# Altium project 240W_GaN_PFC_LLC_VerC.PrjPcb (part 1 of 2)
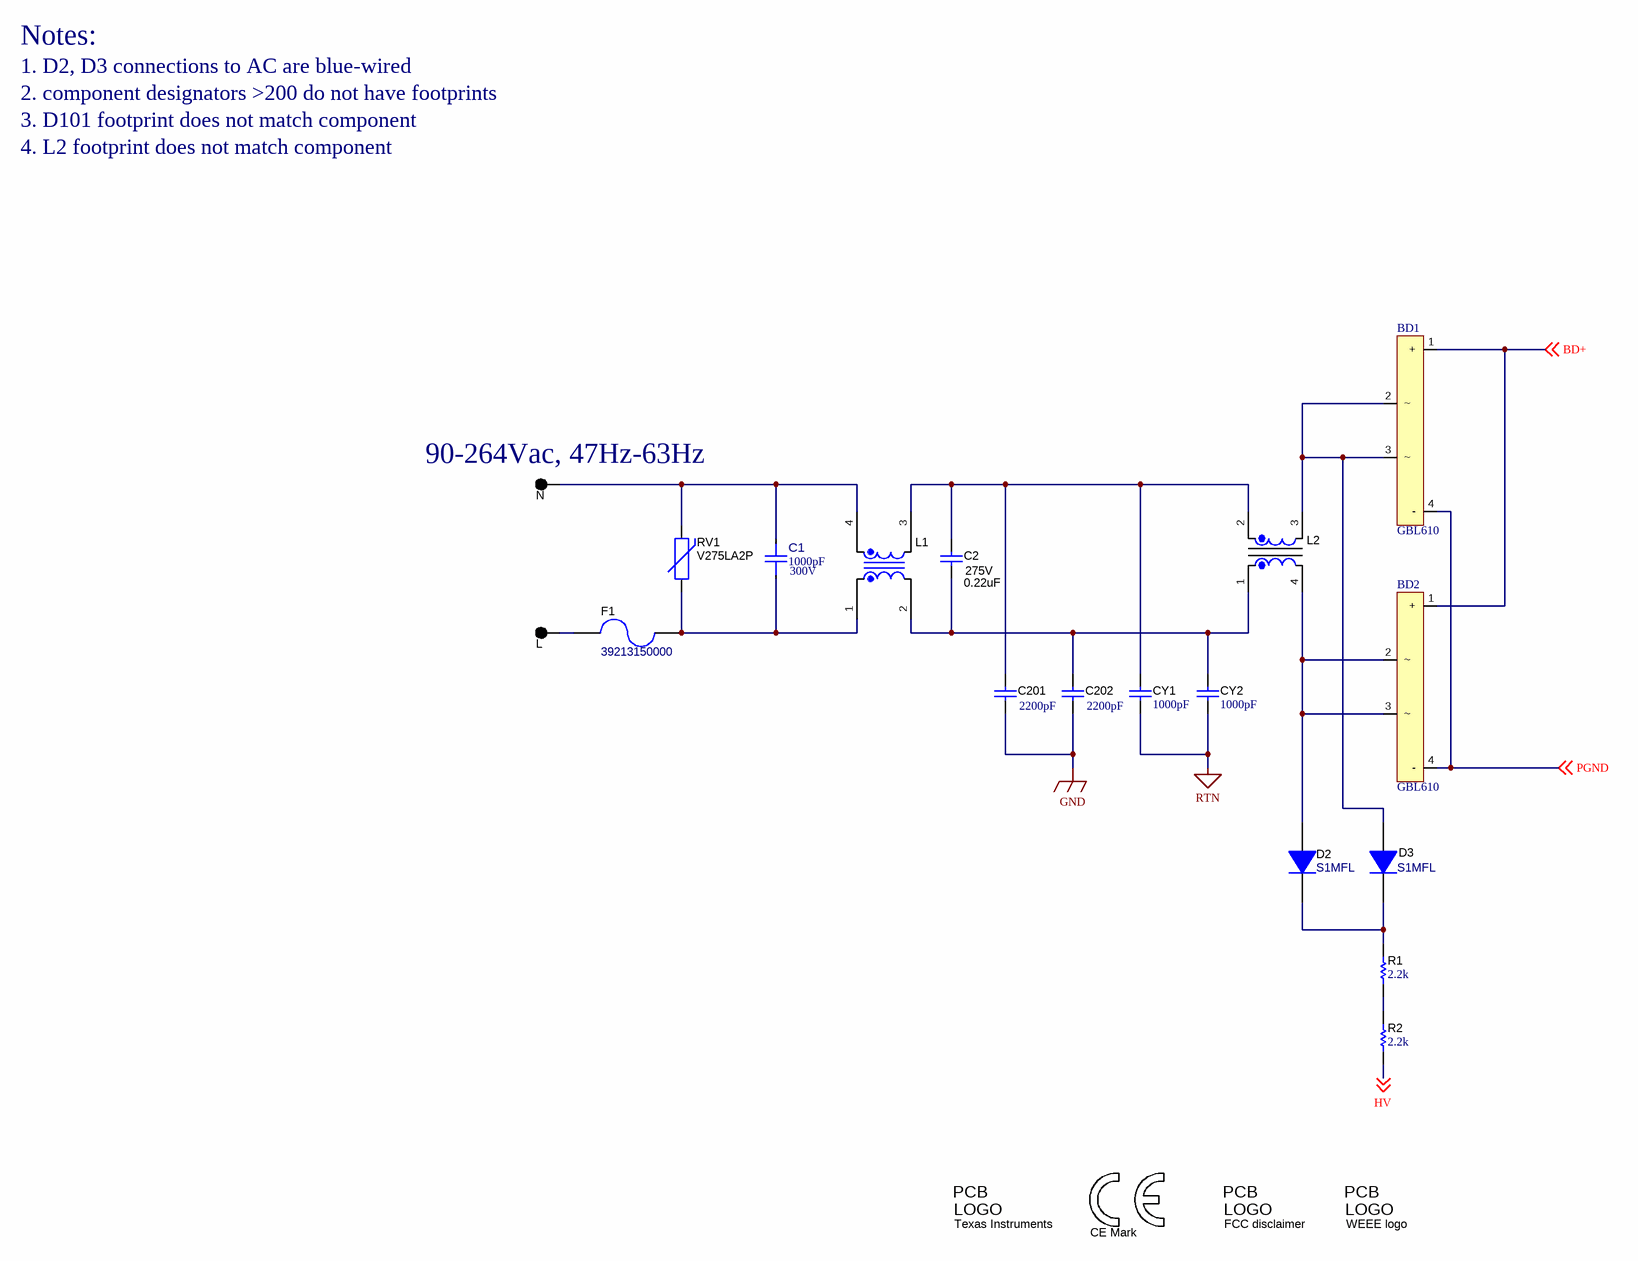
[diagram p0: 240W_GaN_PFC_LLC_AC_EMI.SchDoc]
CopyrightYear: 2024; PCB_Layout: M. Huang; PCB_Rev: C; PRJ_Engineer: M. Huang / J. Gomez; PRJ_Number: PMP23558; PRJ_Title: 240W PFC + LLC; SCH_Rev: C; TechSupport: http://www.ti.com/support; TID: N/A
3 sheets, 170 parts. Net scope: global (net labels, ports and power ports of the same name join across sheets).
Board file: 240W_GaN_PFC_LLC.PcbDoc
Sheets:
  240W_GaN_PFC_LLC_AC_EMI.SchDoc
  240W_PFC_Stage.SchDoc
  240W_LLC_Stage.SchDoc

## Sheet 240W_GaN_PFC_LLC_AC_EMI.SchDoc
size 431 x 279 mm; Date: Not shown in title block; ApprovedBy: Not shown in title block; CheckedBy: Not shown in title block; Author: Not shown in title block; CompanyName: Not shown in title block; Engineer: Not shown in title block; Organization: Not shown in title block; Address1: Not shown in title block; Address2: Not shown in title block; Address3: Not shown in title block; Address4: Not shown in title block; DocumentNumber: 1; Revision: Use project parameter SCH_Rev; SheetNumber: 1; SheetTotal: 3; PageSetup: Record=PageOptions¦CenterHorizontal=True¦CenterVertical=True¦PrintScale=1.00¦XCorrection=1.00¦YCorrection=1.00¦PrintKind=0¦BorderSize=5000000¦LeftOffset=0¦BottomOffset=0¦Orientation=2¦PaperLength=1000¦PaperWidth=1000¦Scale=100¦PaperSource=15¦PrintQuality=600¦MediaType=1¦DitherType=10¦PaperKind=Letter¦PrintScaleMode=1

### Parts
BD1  GBL610  [GBL610]
BD2  GBL610  [GBL610]
C1  ValueDisplayed: 1000pF  VAC: 300V  [FP-R413D1100JMT0K_RADIAL-MFG]  (hidden comment: R413D1100JMT0K)
C2  VDC_V: 275V  ValueDisplayed: 0.22uF  [WCAP-FTX2_1500x700x1250]  (hidden comment: 890324024002)
C201  ValueDisplayed: 2200pF  [VY2_900x500]  (hidden comment: VY2222M35Y5US63V7)
C202  ValueDisplayed: 2200pF  [VY2_900x500]  (hidden comment: VY2222M35Y5US63V7)
CY1  ValueDisplayed: 1000pF  [DK1_86]  (hidden comment: DK1E3EA102M86RAH01)
CY2  ValueDisplayed: 1000pF  [DK1_86]  (hidden comment: DK1E3EA102M86RAH01)
D2  S1MFL  [SOD-123]
D3  S1MFL  [SOD-123]
F1  39213150000  [FUSE_392]
L1  744842565  [WE-CMB_NiZn_S]  (value not drawn)
L2  (no value)  [CM_DCN181713H]
Logo1  CE Mark  [CE_Mark_5mm]  (no BOM)
Logo2  Texas Instruments  [TI_Stacked_Overlay_Small]  (no BOM)
Logo3  FCC disclaimer  [FCC_disclaimer]  (no BOM)
Logo4  WEEE logo  [WEEE_Minimum]  (no BOM)
R1  ValueDisplayed: 2.2k  [1206]  (hidden comment: CRCW12062K20JNEA)
R2  ValueDisplayed: 2.2k  [1206]  (hidden comment: CRCW12062K20JNEA)
RV1  V275LA2P  [Littelfuse_V275LA_7MM]
TP1  N  [Keystone5011]
TP2  L  [Keystone5011]

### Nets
GND: C201.2 C202.2
PGND: BD1.4(-) BD2.4(-) ; off-sheet PGND
RTN: CY1.2 CY2.2
BD+: BD1.1(+) BD2.1(+) ; off-sheet BD+
HV: R2.1 ; off-sheet HV
NetBD1_2: BD1.2 BD1.3 D3.2(A) L2.3
NetBD2_2: BD2.2 BD2.3 D2.2(A) L2.4
NetC1_1: C1.1 F1.1 L1.1 RV1.1
NetC1_2: C1.2 L1.4 RV1.2 TP1.1
NetC2_1: C2.1 C201.1 CY1.1 L1.3 L2.2
NetC2_2: C2.2 C202.1 CY2.1 L1.2 L2.1
NetD2_1: D2.1(K) D3.1(K) R1.2
NetF1_2: F1.2 TP2.1
NetR1_1: R1.1 R2.2

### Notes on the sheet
- Notes:
- 1. D2, D3 connections to AC are blue-wired
- 2. component designators >200 do not have footprints
- 3. D101 footprint does not match component
- 4. L2 footprint does not match component
- (near TP1) 90-264Vac, 47Hz-63Hz

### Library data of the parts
BD1 BD2 = BD
C1 = CMP-0047964-1: 1000 pF Film Capacitor 300V 1500V (1.5kV) Polypropylene (PP), Metallized Radial; Manufacturer: KEMET; AEC Grade: Grade 1; AEC Qualified: Yes; Cap_F: 1nF; SizeZ_mm: 9.1mm; Tolerance_%: 10%; VAC_X: X1; VAC_Y: Y2; Value: 1nF
C2 = CMP-0012312-3: CAP, Film, 0.22 uF, 275 V, +/- 10%, TH; Manufacturer: Wurth Elektronik; TaMin_C: -40°C; Polarized: N; SizeAreaWB_mm2: 153; Value1: Unknown; Value: 0.22uF; TaMax_C: 105°C; SizeZ_mm: 13; SizeX_mm: 15; SizeY_mm: 7; Cap_Case: 15x7x12.5; SizeArea_mm2: 105; Cap_F: 220nF; AEC Category: Q200
C201 C202 = CMP-0009627-2: CAP, CERM, 2200 pF, 440 V, +/- 20%, VY2, D9xT5mm; Manufacturer: Vishay-Bccomponents; TaMin_C: -40°C; Polarized: N; SizeAreaWB_mm2: 77; Value1: Unknown; U/M: EA; Value: 2200pF; TaMax_C: 125°C; SizeZ_mm: 13; SizeX_mm: 9; SizeY_mm: 5; Cap_Case: 9x5mm; Value2: 440V; SizeArea_mm2: 45; Cap_F: 2.2nF; AEC Category: Q200
CY1 CY2 = CMP-0077997-1: CAP, CERM, 1000 pF, X1 440 VAC/Y1 250 VAC, +/- 20%, E, 8x6mm; Manufacturer: MuRata; Cap_F: 1nF; VAC_X: 440; SizeAreaWB_mm2: 107.2; VAC_Y: 250; SizeArea_mm2: 68.4; AEC Qualified: N; AEC Category: Q200; Value: 1000pF; TaMax_C: 125°C; SizeZ_mm: 2.5; TaMin_C: -40°C; SizeY_mm: 6; U/M: EA; AC_Safety: X1Y1; SizeX_mm: 11.4
D2 D3 = CMP-0029032-2: Diode, GP, 1KV, 1 A, SOD-123F; Manufacturer: ON Semiconductor; Value: 1000V; Type: Switching; SizeY_mm: 1.7; Io_A: 1A; SizeAreaWB_mm2: 13.095; SizeArea_mm2: 6.545; Vf_V: 1V; TJmax_C: 150°C; SizeX_mm: 3.85; SizeZ_mm: 1.35; Green_Lifecycle: Active; Green_REACh: Passed
F1 = CMP-0003561-2: Fuse, 3.15 A, 250VAC/VDC, TH; Manufacturer: Littelfuse; Irating_A: 3.15A; VAC_V: 250V
L1 = CMP-0013095-2: Coupled inductor, 5 A, 0.013 ohm, TH; Manufacturer: Wurth Elektronik; DCR_ohm: 0.013
L2 = CM_Choke_Planar: Manufacturer: Wurth; PartNumber: 744824310
Logo1 = CMP-0074844-1: SymbolCreator: a0412235
Logo2 = CMP-0074838-1: Texas Instrument Corporate Signature; SymbolCreator: a0412235; Lib Reference: TI_Logo; Library Reference: Logo
Logo3 = CMP-0074847-1: FCC_disclaimer; Library Reference: Logo
Logo4 = CMP-0074769-1
R1 R2 = CMP-0018641-3: RES, 2.2 k, 5%, 0.25 W, AEC-Q200 Grade 0, 1206; Manufacturer: Vishay-Dale; Power_W: 250mW; TempCo: 200 ppm/C; Value_Code: 2k20; Value: 2.2k; EIA_Code: E24; SizeX_mm: 3.2; SizeY_mm: 1.6; SizeZ_mm: 1.35; Value2: 0.25W; SizeArea_mm2: 5.12; AEC Qualified: Y; VDC_V: 200V; AEC Category: Q200; AEC Grade: 0
RV1 = CMP-0001908-4: VARISTOR 450V 1.2KA DISC 7MM; Manufacturer: Littelfuse; SizeX_mm: 7; SizeArea_mm2: 39.2; SizeY_mm: 5.6; SizeAreaWB_mm2: 68.4; SizeZ_mm: 12
TP1 TP2 = CMP-0055148-1: Test Point, Multipurpose, Black, TH; Manufacturer: Keystone; CNHeader: FALSE; Green_Lifecycle: Active; Green_REACh: Passed; ContactFinish: Silver; CT: TRUE

## Sheet 240W_PFC_Stage.SchDoc
size 431 x 279 mm; Date: Not shown in title block; ApprovedBy: Not shown in title block; CheckedBy: Not shown in title block; Author: Not shown in title block; CompanyName: Not shown in title block; Engineer: Not shown in title block; Organization: Not shown in title block; Address1: Not shown in title block; Address2: Not shown in title block; Address3: Not shown in title block; Address4: Not shown in title block; DocumentNumber: 2; Revision: Use project parameter SCH_Rev; SheetNumber: 2; SheetTotal: 3; PageSetup: Record=PageOptions¦CenterHorizontal=True¦CenterVertical=True¦PrintScale=1.00¦XCorrection=1.00¦YCorrection=1.00¦PrintKind=0¦BorderSize=5000000¦LeftOffset=0¦BottomOffset=0¦Orientation=2¦PaperLength=1000¦PaperWidth=1000¦Scale=100¦PaperSource=15¦PrintQuality=600¦MediaType=1¦DitherType=10¦PaperKind=Letter¦PrintScaleMode=1
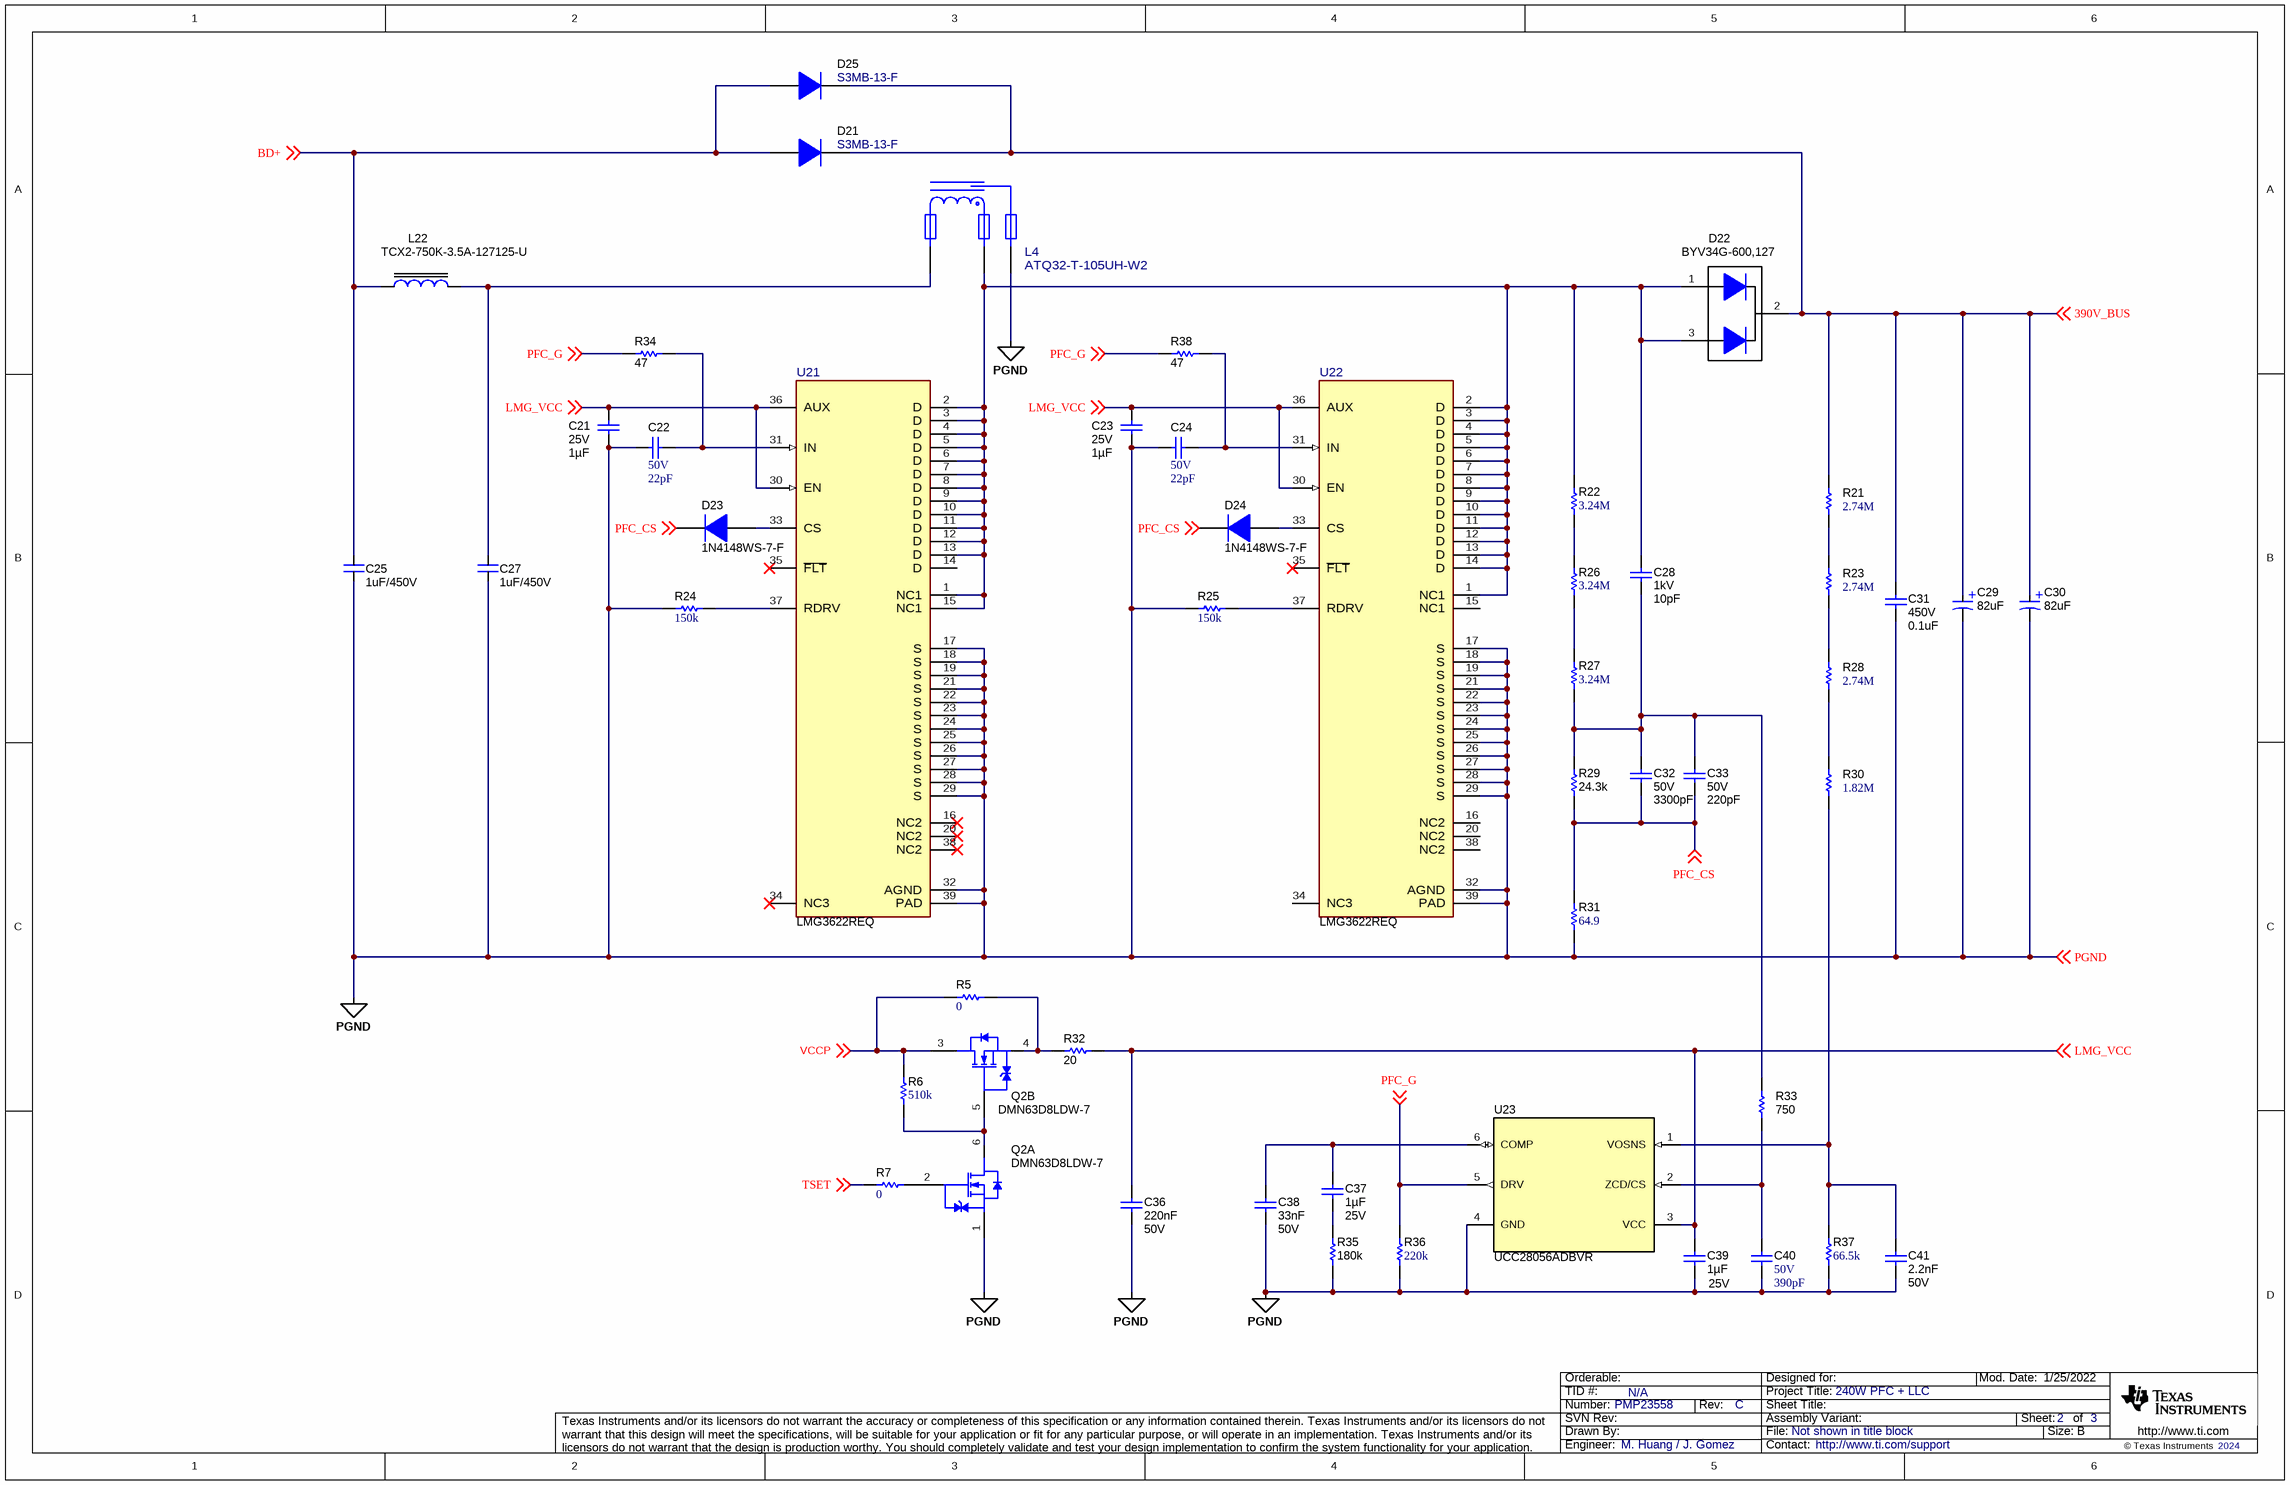
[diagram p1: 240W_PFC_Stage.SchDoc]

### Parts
C21  Cap_F: 1µF  VDC_V: 25V  [0603_HV]  (hidden comment: GRJ188R71E105KE11D)
C22  VDC_V: 50V  ValueDisplayed: 22pF  [0603_HV]  (hidden comment: CGA3E2C0G1H220J080AA)
C23  Cap_F: 1µF  VDC_V: 25V  [0603_HV]  (hidden comment: GRJ188R71E105KE11D)
C24  VDC_V: 50V  ValueDisplayed: 22pF  [0603_HV]  (hidden comment: CGA3E2C0G1H220J080AA)
C25  1uF/450V  [C_film_17.5x7]
C27  1uF/450V  [C_film_17.5x7]
C28  VDC_V: 1kV  ValueDisplayed: 10pF  [1206L]  (hidden comment: VJ1206A100JXGAT5Z)
C29  82uF  [Cap_12.5x40_H1]
C30  82uF  [Cap_12.5x40_H1]
C31  VDC_V: 450V  ValueDisplayed: 0.1uF  [1206_180]  (hidden comment: C3216X7T2W104K160AE)
C32  VDC_V: 50V  ValueDisplayed: 3300pF  [0603_HV]  (hidden comment: GRM1885C1H332JA01D)
C33  VDC_V: 50V  ValueDisplayed: 220pF  [0603_HV]  (hidden comment: GRM1885C1H221JA01D)
C36  Cap_F: 220nF  VDC_V: 50V  [0603_HV]  (hidden comment: GCM188R71H224KA64D)
C37  Cap_F: 1µF  VDC_V: 25V  [0603_HV]  (hidden comment: 06033C105KAT2A)
C38  Cap_F: 33nF  VDC_V: 50V  [0603_HV]  (hidden comment: GRM188R71H333KA61D)
C39  Cap_F: 1µF  VDC_V: 25V  [0603_HV]  (hidden comment: 06033C105KAT2A)
C40  VDC_V: 50V  ValueDisplayed: 390pF  [0603_HV]  (hidden comment: C0603C391J5GACTU)
C41  Cap_F: 2.2nF  VDC_V: 50V  [0603_HV]  (hidden comment: C0603C222K5RACTU)
D21  S3MB-13-F  [SMB]
D22  BYV34G-600,127  [TO-220AB]
D23  1N4148WS-7-F  [SOD-323]
D24  1N4148WS-7-F  [SOD-323]
D25  S3MB-13-F  [SMB]
L4  ATQ32-T-105UH-W2  [FP-202410103L250W_PTH3-MFG]
L22  TCX2-750K-3.5A-127125-U  [L_Ring_H_D=16.76mm]
Q2  DMN63D8LDW-7  [SOT-363]  (parts A,B of 2)
R5  ValueDisplayed: 0  [0603_HV]  (hidden comment: RCS06030000Z0EA)
R6  ValueDisplayed: 510k  [0603_HV]  (hidden comment: CRCW0603510KJNEA)
R7  ValueDisplayed: 0  [0603_HV]  (hidden comment: RCS06030000Z0EA)
R21  ValueDisplayed: 2.74M  [0805_HV]  (hidden comment: CRCW08052M74FKEA)
R22  ValueDisplayed: 3.24M  [0805_HV]  (hidden comment: CRCW08053M24FKEA)
R23  ValueDisplayed: 2.74M  [0805_HV]  (hidden comment: CRCW08052M74FKEA)
R24  ValueDisplayed: 150k  [0603_HV]  (hidden comment: CRCW0603150KJNEA)
R25  ValueDisplayed: 150k  [0603_HV]  (hidden comment: CRCW0603150KJNEA)
R26  ValueDisplayed: 3.24M  [0805_HV]  (hidden comment: CRCW08053M24FKEA)
R27  ValueDisplayed: 3.24M  [0805_HV]  (hidden comment: CRCW08053M24FKEA)
R28  ValueDisplayed: 2.74M  [0805_HV]  (hidden comment: CRCW08052M74FKEA)
R29  ValueDisplayed: 24.3k  [0603_HV]  (hidden comment: RC0603FR-0724K3L)
R30  ValueDisplayed: 1.82M  [0805_HV]  (hidden comment: CRCW08051M82FKEA)
R31  ValueDisplayed: 64.9  [0603]  (hidden comment: RC0603FR-0764R9L)
R32  ValueDisplayed: 20  [0603_HV]  (hidden comment: CRCW060320R0JNEA)
R33  ValueDisplayed: 750  [0603_HV]  (hidden comment: RC0603JR-07750RL)
R34  ValueDisplayed: 47  [0603_HV]  (hidden comment: CRCW060347R0JNEA)
R35  ValueDisplayed: 180k  [0603_HV]  (hidden comment: CRCW0603180KJNEA)
R36  ValueDisplayed: 220k  [0603_HV]  (hidden comment: CRCW0603220KJNEA)
R37  ValueDisplayed: 66.5k  [0603_HV]  (hidden comment: RC0603FR-0766K5L)
R38  ValueDisplayed: 47  [0603_HV]  (hidden comment: CRCW060347R0JNEA)
U21  LMG3622REQ  [REQ0038A-MFG]
U22  LMG3622REQ  [REQ0038A-MFG]
U23  UCC28056ADBVR  [DBV0006A_N]

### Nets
PGND: C21.1 C22.2 C23.1 C24.2 C25.2 C27.2 C29.2(N) C30.2(N) C31.2 C36.2 C38.2 C39.2 C40.2 C41.2 L4.3 Q2.1(S) R24.1 R25.1 R31.1 R35.1 R36.1 R37.1 U21.17(S) U21.18(S) U21.19(S) U21.21(S) U21.22(S) U21.23(S) U21.24(S) U21.25(S) U21.26(S) U21.27(S) U21.28(S) U21.29(S) U21.32(AGND) U21.39(PAD) U22.17(S) U22.18(S) U22.19(S) U22.21(S) U22.22(S) U22.23(S) U22.24(S) U22.25(S) U22.26(S) U22.27(S) U22.28(S) U22.29(S) U22.32(AGND) U22.39(PAD) U23.4(GND) ; off-sheet PGND
390V_BUS: C29.1(P) C30.1(P) C31.1 D21.1(K) D22.2(K) D25.1(K) R21.2 ; off-sheet 390V_BUS
BD+: C25.1 D21.2(A) D25.2(A) L22.1 ; off-sheet BD+
LMG_VCC: C21.2 C23.2 C36.1 C39.1 R32.1 U21.30(EN) U21.36(AUX) U22.30(EN) U22.36(AUX) U23.3(VCC) ; off-sheet LMG_VCC
PFC_CS: C32.2 C33.2 D23.1(K) D24.1(K) R29.1 R31.2 ; off-sheet PFC_CS
PFC_G: R34.1 R36.2 R38.2 U23.5(DRV) ; off-sheet PFC_G
TSET: R7.1 ; off-sheet TSET
VCCP: Q2.3(D) R5.1 R6.2 ; off-sheet VCCP
NetC22_1: C22.1 R34.2 U21.31(IN)
NetC24_1: C24.1 R38.1 U22.31(IN)
NetC27_1: C27.1 L4.2 L22.2
NetC28_1: C28.1 D22.1(A) D22.3(A) L4.4 R22.2 U21.1(NC1) U21.2(D) U21.3(D) U21.4(D) U21.5(D) U21.6(D) U21.7(D) U21.8(D) U21.9(D) U21.10(D) U21.11(D) U21.12(D) U21.13(D) U21.15(NC1) U22.1(NC1) U22.2(D) U22.3(D) U22.4(D) U22.5(D) U22.6(D) U22.7(D) U22.8(D) U22.9(D) U22.10(D) U22.11(D) U22.12(D) U22.13(D) U22.14(D)
NetC28_2: C28.2 C32.1 C33.1 R27.1 R29.2 R33.2
NetC37_1: C37.1 C38.1 U23.6(COMP)
NetC37_2: C37.2 R35.2
NetC40_1: C40.1 R33.1 U23.2(ZCD/CS)
NetC41_1: C41.1 R30.1 R37.2 U23.1(VOSNS)
NetD23_2: D23.2(A) U21.33(CS)
NetD24_2: D24.2(A) U22.33(CS)
NetQ2_2: Q2.2(G) R7.2
NetQ2_4: Q2.4(S) R5.2 R32.2
NetQ2_5: Q2.5(G) Q2.6(D) R6.1
NetR21_1: R21.1 R23.2
NetR22_1: R22.1 R26.2
NetR23_1: R23.1 R28.2
NetR24_2: R24.2 U21.37(RDRV)
NetR25_2: R25.2 U22.37(RDRV)
NetR26_1: R26.1 R27.2
NetR28_1: R28.1 R30.2

Not connected (* = marked no-connect by the designer): U21 14(D) 16(NC2)* 20(NC2)* 34(NC3)* 35(~{FLT})* 38(NC2)*; U22 15(NC1) 16(NC2) 20(NC2) 34(NC3) 35(~{FLT})* 38(NC2)

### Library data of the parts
C21 C23 = CMP-0079720-1: CAP, CERM, 1 µF, 25 V,+/- 10%, X7R, 0603; Manufacturer: MuRata; TaMin_C: -55°C; Polarized: N; SizeAreaWB_mm2: 4.68; U/M: EA; Value: 1uF; TaMax_C: 125°C; SizeZ_mm: 1; SizeX_mm: 1.6; SizeY_mm: 0.8; Cap_Case: 0603; SizeArea_mm2: 1.28; AEC Category: Q200
C22 C24 = CMP-0007071-4: CAP, CERM, 22 pF, 50 V, +/- 5%, C0G/NP0, AEC-Q200 Grade 1, 0603; Manufacturer: TDK; TaMin_C: -55°C; Polarized: N; SizeAreaWB_mm2: 4.68; Value1: Unknown; U/M: EA; Value: 22pF; TaMax_C: 125°C; SizeZ_mm: 1; SizeX_mm: 1.6; SizeY_mm: 0.8; Cap_Case: 0603; SizeArea_mm2: 1.28; AEC Qualified: Y; AEC Category: Q200
C25 C27 = C_film: Manufacturer: Used in BOM report; CompType: Used in some BOM reports.  Useful for finding later.
C28 = CMP-0009029-2: CAP, CERM, 10 pF, 1000 V, +/- 5%, C0G/NP0, 1206; Manufacturer: Vishay-Vitramon; TaMin_C: -55°C; Polarized: N; SizeAreaWB_mm2: 10.92; Value1: Unknown; U/M: EA; Value: 10pF; TaMax_C: 125°C; SizeZ_mm: 1.35; SizeX_mm: 3.2; SizeY_mm: 1.6; Cap_Case: 1206; Value2: 1000V; SizeArea_mm2: 5.12; AEC Category: Q200
C29 C30 = E-Cap: EKXN451ELL820MK40S; Manufacturer: Used in BOM report; CompType: Used in some BOM reports.  Useful for finding later.
C31 = CMP-0008728-1: CAP, CERM, 0.1 uF, 450 V, +/- 10%, X7T, 1206; Manufacturer: TDK; TaMin_C: -55°C; Polarized: N; SizeAreaWB_mm2: 10.92; Value1: Unknown; U/M: EA; Value: 0.1uF; TaMax_C: 125°C; SizeZ_mm: 1.8; SizeX_mm: 3.2; SizeY_mm: 1.6; Cap_Case: 1206; SizeArea_mm2: 5.12; Cap_F: 100nF; AEC Category: Q200
C32 = CMP-0007210-1: CAP, CERM, 3300 pF, 50 V, +/- 5%, C0G/NP0, 0603; Manufacturer: MuRata; TaMin_C: -55°C; Polarized: N; SizeAreaWB_mm2: 4.68; Value1: Unknown; U/M: EA; Value: 3300pF; TaMax_C: 125°C; SizeZ_mm: 1; SizeX_mm: 1.6; SizeY_mm: 0.8; Cap_Case: 0603; SizeArea_mm2: 1.28; Cap_F: 3.3nF; AEC Category: Q200
C33 = CMP-0007197-4: CAP, CERM, 220 pF, 50 V, +/- 5%, C0G/NP0, 0603; Manufacturer: MuRata; TaMin_C: -55°C; Polarized: N; SizeAreaWB_mm2: 4.68; Value1: Unknown; U/M: EA; Value: 220pF; TaMax_C: 125°C; SizeZ_mm: 1; SizeX_mm: 1.6; SizeY_mm: 0.8; Cap_Case: 0603; SizeArea_mm2: 1.28; AEC Category: Q200
C36 = CMP-0007145-3: CAP, CERM, 0.22 uF, 50 V, +/- 10%, X7R, AEC-Q200 Grade 1, 0603; Manufacturer: MuRata; TaMin_C: -55°C; Polarized: N; SizeAreaWB_mm2: 4.68; Value1: Unknown; U/M: EA; Value: 0.22uF; TaMax_C: 125°C; SizeZ_mm: 1; SizeX_mm: 1.6; SizeY_mm: 0.8; Cap_Case: 0603; SizeArea_mm2: 1.28; AEC Qualified: Y; AEC Category: Q200
C37 C39 = CMP-0006754-4: CAP, CERM, 1 uF, 25 V, +/- 10%, X7R, 0603; Manufacturer: AVX; TaMin_C: -55°C; Polarized: N; SizeAreaWB_mm2: 4.68; Value1: Unknown; U/M: EA; Value: 1uF; TaMax_C: 125°C; SizeZ_mm: 1; SizeX_mm: 1.6; SizeY_mm: 0.8; Cap_Case: 0603; SizeArea_mm2: 1.28; AEC Category: Q200
C38 = CMP-0007451-3: CAP, CERM, 0.033 uF, 50 V, +/- 10%, X7R, 0603; Manufacturer: MuRata; TaMin_C: -55°C; Polarized: N; SizeAreaWB_mm2: 4.68; Value1: Unknown; U/M: EA; TaMax_C: 125°C; SizeZ_mm: 1; SizeX_mm: 1.6; SizeY_mm: 0.8; Cap_Case: 0603; SizeArea_mm2: 1.28; AEC Category: Q200
C40 = CMP-0006932-4: CAP, CERM, 390 pF, 50 V, +/- 5%, C0G/NP0, 0603; Manufacturer: Kemet; TaMin_C: -55°C; Polarized: N; SizeAreaWB_mm2: 4.68; Value1: Unknown; U/M: EA; Value: 390pF; TaMax_C: 125°C; SizeZ_mm: 1; SizeX_mm: 1.6; SizeY_mm: 0.8; Cap_Case: 0603; SizeArea_mm2: 1.28; AEC Category: Q200
C41 = CMP-0006898-4: CAP, CERM, 2200 pF, 50 V, +/- 10%, X7R, 0603; Manufacturer: Kemet; TaMin_C: -55°C; Polarized: N; SizeAreaWB_mm2: 4.68; Value1: Unknown; U/M: EA; Value: 2200pF; TaMax_C: 125°C; SizeZ_mm: 1; SizeX_mm: 1.6; SizeY_mm: 0.8; Cap_Case: 0603; SizeArea_mm2: 1.28; AEC Category: Q200
D21 D25 = CMP-0077014-1: Diode, GP, 1000V, 3 A, SMB; Manufacturer: Diodes Incorporated; SizeAreaWB_mm2: 44.156; SizeArea_mm2: 21.336; TJmax_C: 175°C; AEC Category: Q101; SizeZ_mm: 2.6; Green_REACh: Incomplete; Io_A: 3A; Vf_V: 1.3V; SizeY_mm: 3.81; Green_Lifecycle: Not Set; U/M: EA; SizeX_mm: 5.6; Type: Ultrafast
D22 = CMP-0085337-1: Diode, Ultrafast, 600 V, 8 A, TO-220AB; Manufacturer: ON Semiconductor; AEC Qualified: N; AEC Category: Q101; SizeAreaWB_mm2: 79.3; Vr_V: 600V; SizeArea_mm2: 45.9; TJmax_C: 175°C; Value2: 16V; SizeY_mm: 4.5; RJC_CperW: 2; SizeX_mm: 10.2; Value: 600V; Io_A: 8A; SizeZ_mm: 19.4
D23 D24 = CMP-0079597-2: Diode, Switching, 75 V, 0.15 A, AEC-Q101, SOD-323; Manufacturer: Diodes Inc.; SizeX_mm: 2.7; Vf_V: 1.25V; AEC Qualified: Y; SizeArea_mm2: 3.645; AEC Category: Q101; SizeAreaWB_mm2: 8.695; Io_A: 150mA; SizeZ_mm: 1; Value1: 0.15A; SizeY_mm: 1.35; TJmax_C: 150°C; Vr_V: 75V; Value: 75V
L4 = CMP-0124119-1: 250W  PFC Inductor; Manufacturer: 3L; PartNumber: 202410103L250W; AEC Qualified: No; DCR_ohm: 25.5m; Ind_H: 105µH; SizeZ_mm: 14mm; Value: 105uH; Test Frequency: 10kHz; Tolerance_%: 10%
L22 = L_FIX: Manufacturer: Used in BOM report; CompType: Used in some BOM reports.  Useful for finding later.
Q2 = CMP-0000615-1: MOSFET, 2-CH, N-CH, 30 V, 0.22 A, AEC-Q101, SOT-363; Alternate Manufacturer: None; Manufacturer: Diodes Inc.; SizeZ_mm: 1.1; ChType: N; Value2: 0.43 nC; Value1: 4; VdsMax_V: 30V; SizeX_mm: 2.2; Vgs_V: 20V; AEC Qualified: Y; Value: 30V; Rdson45_ohm: 4.2; SizeArea_mm2: 4.84; AEC Category: Q101; IdsMax_A: 220mA; SizeAreaWB_mm2: 10.24; U/M: EA; QgTyp_nC: 0.43
R5 R7 = CMP-0081973-1: RES, 0, 0%, 0.25 W, AEC-Q200 Grade 0, 0603; Manufacturer: Vishay-Dale; SizeAreaWB_mm2: 4.68; SizeArea_mm2: 1.28; AEC Qualified: Y; AEC Category: Q200; Value: 0; SizeZ_mm: 1; SizeY_mm: 0.8; Power_W: 250mW; Value2: 0.25W; SizeX_mm: 1.6
R6 = CMP-0025822-1: RES, 510 k, 5%, 0.1 W, 0603; Manufacturer: Vishay-Dale; Power_W: 100mW; TempCo: 200 ppm/C; U/M: EA; Value: 510k; EIA_Code: E24; SizeX_mm: 1.6; SizeY_mm: 0.8; SizeZ_mm: 1; Value2: 0.1W; SizeArea_mm2: 1.28; VDC_V: 75V; AEC Category: Q200
R21 R23 R28 = CMP-0021137-3: RES, 2.74 M, 1%, 0.125 W, AEC-Q200 Grade 0, 0805; Manufacturer: Vishay-Dale; Power_W: 125mW; TempCo: 100 ppm/C; Value_Code: 2M74; Value: 2.74Meg; EIA_Code: E96; SizeX_mm: 2; SizeY_mm: 1.25; SizeZ_mm: 1.45; Value2: 0.125W; SizeArea_mm2: 2.5; AEC Qualified: Y; VDC_V: 150V; AEC Category: Q200; AEC Grade: 0
R22 R26 R27 = CMP-0021222-4: RES, 3.24 M, 1%, 0.125 W, AEC-Q200 Grade 0, 0805; Manufacturer: Vishay-Dale; Power_W: 125mW; TempCo: 100 ppm/C; Value_Code: 3M24; Value: 3.24Meg; EIA_Code: E96; SizeX_mm: 2; SizeY_mm: 1.25; SizeZ_mm: 1.45; Value2: 0.125W; SizeArea_mm2: 2.5; AEC Qualified: Y; VDC_V: 150V; AEC Category: Q200; AEC Grade: 0
R24 R25 = CMP-0025717-4: RES, 150 k, 5%, 0.1 W, AEC-Q200 Grade 0, 0603; Manufacturer: Vishay-Dale; Power_W: 100mW; TempCo: 200 ppm/C; Value: 150k; EIA_Code: E24; SizeX_mm: 1.6; SizeY_mm: 0.8; SizeZ_mm: 1; Value2: 0.1W; SizeArea_mm2: 1.28; AEC Qualified: Y; VDC_V: 75V; AEC Category: Q200; AEC Grade: 0
R29 = CMP-0022943-5: RES, 24.3 k, 1%, 0.1 W, 0603; Manufacturer: Yageo; Power_W: 100mW; TempCo: 100 ppm/C; Value_Code: 24k3; Value: 24.3k; EIA_Code: E96; SizeX_mm: 1.6; SizeY_mm: 0.8; SizeZ_mm: 1; Value2: 0.1W; SizeArea_mm2: 1.28; AEC Qualified: N; VDC_V: 75V; AEC Category: Q200; SizeAreaWB_mm2: 4.68
R30 = CMP-0021005-3: RES, 1.82 M, 1%, 0.125 W, AEC-Q200 Grade 0, 0805; Manufacturer: Vishay-Dale; Power_W: 125mW; TempCo: 100 ppm/C; Value_Code: 1M82; Value: 1.82Meg; EIA_Code: E96; SizeX_mm: 2; SizeY_mm: 1.25; SizeZ_mm: 1.45; Value2: 0.125W; SizeArea_mm2: 2.5; AEC Qualified: Y; VDC_V: 150V; AEC Category: Q200; AEC Grade: 0
R31 = CMP-0023229-5: RES, 64.9, 1%, 0.1 W, 0603; Manufacturer: Yageo; Power_W: 100mW; TempCo: 100 ppm/C; Value_Code: 64R9; Value: 64.9; EIA_Code: E96; SizeX_mm: 1.6; SizeY_mm: 0.8; SizeZ_mm: 1; Value2: 0.1W; SizeArea_mm2: 1.28; AEC Qualified: N; VDC_V: 75V; AEC Category: Q200; SizeAreaWB_mm2: 4.68
R32 = CMP-0025754-1: RES, 20, 5%, 0.1 W, 0603; Manufacturer: Vishay-Dale; Power_W: 100mW; TempCo: 200 ppm/C; Value_Code: 20R0; U/M: EA; Value: 20; EIA_Code: E24; SizeX_mm: 1.6; SizeY_mm: 0.8; SizeZ_mm: 1; Value2: 0.1W; SizeArea_mm2: 1.28; VDC_V: 75V; AEC Category: Q200
R33 = CMP-0025939-5: RES, 750, 5%, 0.1 W, 0603; Manufacturer: Yageo; Power_W: 100mW; TempCo: 100 ppm/C; Value_Code: 750R; Value: 750; EIA_Code: E24; SizeX_mm: 1.6; SizeY_mm: 0.8; SizeZ_mm: 1; Value2: 0.1W; SizeArea_mm2: 1.28; AEC Qualified: N; VDC_V: 75V; AEC Category: Q200; SizeAreaWB_mm2: 4.68
R34 R38 = CMP-0025815-4: RES, 47, 5%, 0.1 W, AEC-Q200 Grade 0, 0603; Manufacturer: Vishay-Dale; Power_W: 100mW; TempCo: 200 ppm/C; Value_Code: 47R0; Value: 47; EIA_Code: E24; SizeX_mm: 1.6; SizeY_mm: 0.8; SizeZ_mm: 1; Value2: 0.1W; SizeArea_mm2: 1.28; AEC Qualified: Y; VDC_V: 75V; AEC Category: Q200; AEC Grade: 0
R35 = CMP-0025725-2: RES, 180 k, 5%, 0.1 W, 0603; Manufacturer: Vishay-Dale; Power_W: 100mW; TempCo: 200 ppm/C; U/M: EA; Value: 180k; EIA_Code: E24; SizeX_mm: 1.6; SizeY_mm: 0.8; SizeZ_mm: 1; Value2: 0.1W; SizeArea_mm2: 1.28; VDC_V: 75V; AEC Category: Q200
R36 = CMP-0025755-4: RES, 220 k, 5%, 0.1 W, AEC-Q200 Grade 0, 0603; Manufacturer: Vishay-Dale; Power_W: 100mW; TempCo: 200 ppm/C; Value: 220k; EIA_Code: E24; SizeX_mm: 1.6; SizeY_mm: 0.8; SizeZ_mm: 1; Value2: 0.1W; SizeArea_mm2: 1.28; AEC Qualified: Y; VDC_V: 75V; AEC Category: Q200; AEC Grade: 0
R37 = CMP-0023232-5: RES, 66.5 k, 1%, 0.1 W, 0603; Manufacturer: Yageo; Power_W: 100mW; TempCo: 100 ppm/C; Value_Code: 66k5; Value: 66.5k; EIA_Code: E96; SizeZ_mm: 1; Value2: 0.1W; SizeArea_mm2: 1.28; AEC Qualified: N; VDC_V: 75V; AEC Category: Q200; SizeAreaWB_mm2: 4.68; SizeX_mm: 1.6; SizeY_mm: 0.8
U21 U22 = CMP-0096535-2: 650-V GaN FET With Integrated Driver and Current Sense Emulation; Manufacturer: Texas Instruments; Number Of Drivers: 1; CompType: IC; Max Supply Voltage: 26V; SizeZ_mm: 1mm; AEC Category: Q200; Min Supply Voltage: 10V; AEC Qualified: No; TJmax_C: +175°C; Standoff Height: 0mm
U23 = CMP-0860501-1: 6-Pin Single-Phase Transition-Mode PFC Controller, DBV0006A (SOT-23-6); Alternate Manufacturer: Texas Instruments; SizeY_mm: 2.9; SizeAreaWB_mm2: 14.82; AEC Category: Q200; SizeX_mm: 2.8; Rating: Catalog; SizeArea_mm2: 8.12; CompType: IC; SizeZ_mm: 1.45; AEC Qualified: N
